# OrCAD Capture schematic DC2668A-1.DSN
size Custom; note: 3-20 GHz MICROWAVE MIXER
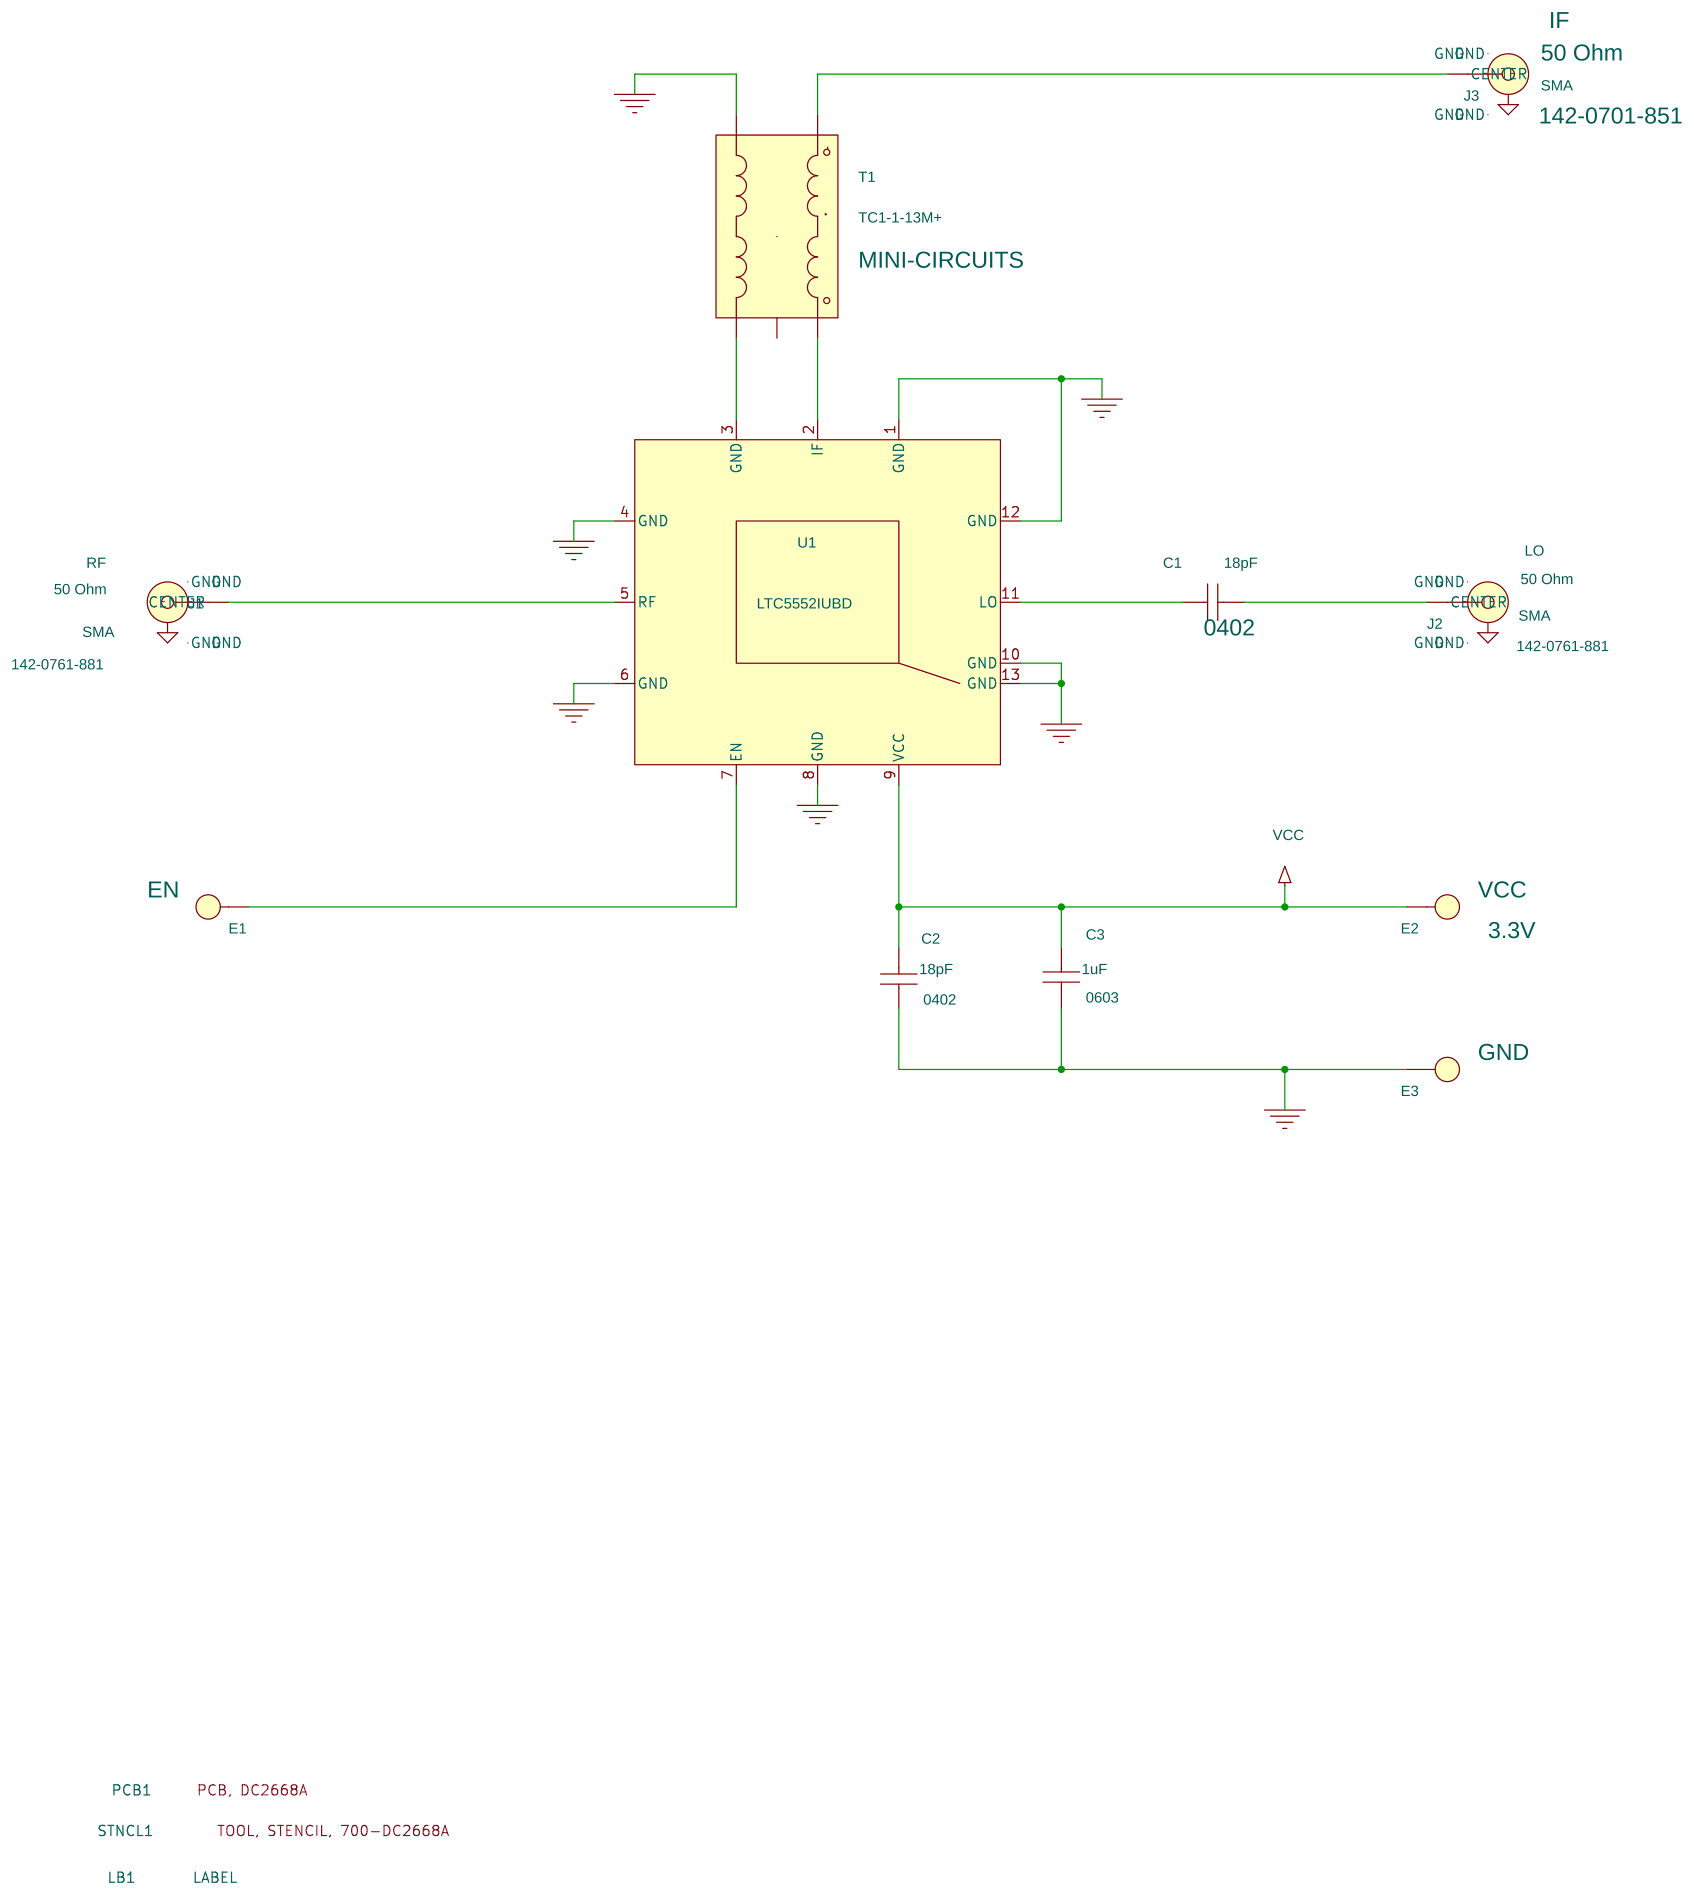
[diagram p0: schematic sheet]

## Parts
C1  18pF  [CC0402N]
C2  18pF  [CC0402N]
C3  1uF  [CC0603N]
E1  TEST POINT  [MILLMAX2308]
E2  TEST POINT  [MILLMAX2308]
E3  TEST POINT  [MILLMAX2308]
J1  SMA  [142-0761-881]
J2  SMA  [142-0761-881]
J3  SMA  [EMERSON_142-0701-851]
LB1  LABEL  [895-0154_REV01]
PCB1  PCB, DC2668A
STNCL1  TOOL, STENCIL, 700-DC2668A
T1  TC1-1-13M+  [MINI-CIRCUITS-TC1-1-13M+]
U1  LTC5552IUBD  [LTC-UDB-12-1941]

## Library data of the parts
C1 = CAP: CAP.,18pF,10V,2%,0402,SINGLE SOURCE ONLY; CLASS: DISCRETE; FPLIST: CC0402N,CC0402L,CC0402M; Manufacturer: AVX; Manufacturer PN: 0402ZK180GBSTR; PART_NUMBER: 150-0575; Package Size: 0402; Rated Voltage: 10V; Tolerance: 2%; UserField01: SINGLE SOURCE ONLY
C2 = CAP: CAP.,18pF,C0G,50V,1%,0402,SINGLE SOURCE ONLY; CLASS: DISCRETE; Dielectric Type: C0G; FPLIST: CC0402N,CC0402L,CC0402M; Manufacturer: MURATA; Manufacturer PN: GJM1555C1H180FB01D; PART_NUMBER: 150-0556; Package Size: 0402; Rated Voltage: 50V; Tolerance: 1%; UserField01: SINGLE SOURCE ONLY
C3 = CAP: CAP.,1uF,X7R,10V,10%,0603,SINGLE SOURCE ONLY; CLASS: DISCRETE; Dielectric Type: X7R; FPLIST: CC0603N,CC0603L,CC0603M; Manufacturer: MURATA; Manufacturer PN: GRM188R71A105KA61D; PART_NUMBER: 150-0557; Package Size: 0603; Rated Voltage: 10V; Tolerance: 10%; UserField01: SINGLE SOURCE ONLY
E1 = TEST_POINT_.156_MILL-MAX_2308: TEST POINT,TURRET,0.064",MTG. HOLE; 1: EN; CLASS: IO; Manufacturer: MILL-MAX; Manufacturer PN: 2308-2-00-80-00-00-07-0; PART_NUMBER: 260-0004
E2 = TEST_POINT_.156_MILL-MAX_2308: TEST POINT,TURRET,0.064",MTG. HOLE; 1: VCC; 2: 3.3V; CLASS: IO; Manufacturer: MILL-MAX; Manufacturer PN: 2308-2-00-80-00-00-07-0; PART_NUMBER: 260-0004
E3 = TEST_POINT_.156_MILL-MAX_2308: TEST POINT,TURRET,0.064",MTG. HOLE; 1: GND; CLASS: IO; Manufacturer: MILL-MAX; Manufacturer PN: 2308-2-00-80-00-00-07-0; PART_NUMBER: 260-0004
J1 = CONN_SMA_5PIN: CONN.,SMA,RCP,13.48mm,THT RA; 1: RF; 2: 50 Ohm; CLASS: IO; Manufacturer: CINCH CONNECTIVITY SOLUTIONS; PART_NUMBER: 250-0645
J2 = CONN_SMA_5PIN: CONN.,SMA,RCP,13.48mm,THT RA; 1: LO; 2: 50 Ohm; CLASS: IO; Manufacturer: CINCH CONNECTIVITY SOLUTIONS; PART_NUMBER: 250-0645
J3 = CONN_SMA_5PIN: CONN.,SMA,JACK, RCPT,END LAUNCH, STR,50 OHMS; 1: IF; 2: 50 Ohm; CLASS: IO; Manufacturer: CINCH CONNECTIVITY SOLUTIONS; Manufacturer PN: 142-0701-851; PART_NUMBER: 250-0446
LB1 = BLANK_LABEL: LABEL SPEC, DEMO BOARD SERIAL NUMBER; Manufacturer: BRADY; Manufacturer PN: THT-96-717-10; PART_NUMBER: 895-0154
PCB1 = BLANK_PCB_PART: CLASS: DISCRETE; Manufacturer: LINEAR TECH.; Manufacturer PN: 600-DC2668A; PART_NUMBER: 600-DC2668A
STNCL1 = BLANK_STENCIL_PART: CLASS: DISCRETE; Manufacturer: LINEAR TECH.; Manufacturer PN: 830-DC2668A; PART_NUMBER: 830-DC2668A
T1 = TRANS-TC1-1-13M+: TRANSFORMER,RF Wideband,1:1,50 OHMS,4.5 - 3000 MHz; 4TH PART FIELD: MINI-CIRCUITS; CLASS: DISCRETE; Manufacturer: MINI-CIRCUITS; PART_NUMBER: 410-0044; Turns Ratio: 1:1
U1 = LTC5552-UDB: IC,3GHz to 20GHz MICROWAVE MIXER,QFN-12-3X2,WITH WIDEBAND DC to 6GHz IF; CLASS: IC; Manufacturer: LINEAR TECH.; Manufacturer PN: LTC5552IUDB#PBF; PART_NUMBER: LTC5552IUDB#PBF; Package Type: QFN-12-3X2

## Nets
GND: C2.1 C3.2 E3.1(A) J1.2(GND) J1.3(GND) J1.4(GND) J1.5(GND) J2.2(GND) J2.3(GND) J2.4(GND) J2.5(GND) J3.2(GND) J3.3(GND) J3.4(GND) J3.5(GND) T1.4 U1.1(GND) U1.4(GND) U1.6(GND) U1.8(GND) U1.10(GND) U1.12(GND) U1.13(GND)
VCC: C2.2 C3.1 E2.1(A) U1.9(VCC)
N16911844: E1.1(A) U1.7(EN)
N16911937: J1.1(CENTER) U1.5(RF)
N16918792: C1.1 U1.11(LO)
N16932384: J3.1(CENTER) T1.6
N16934315: T1.3 U1.3(GND)
N16934318: T1.1 U1.2(IF)
N16936237: C1.2 J2.1(CENTER)

Not connected (* = marked no-connect by the designer): T1 2
